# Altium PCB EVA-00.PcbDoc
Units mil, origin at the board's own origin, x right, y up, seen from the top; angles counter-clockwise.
Board outline 3000 x 2200 mil, 2 copper layers (Top Layer, Bottom Layer), stack 57.918 mil thick; 30 components, 25 nets, 139 pads, 31 vias.
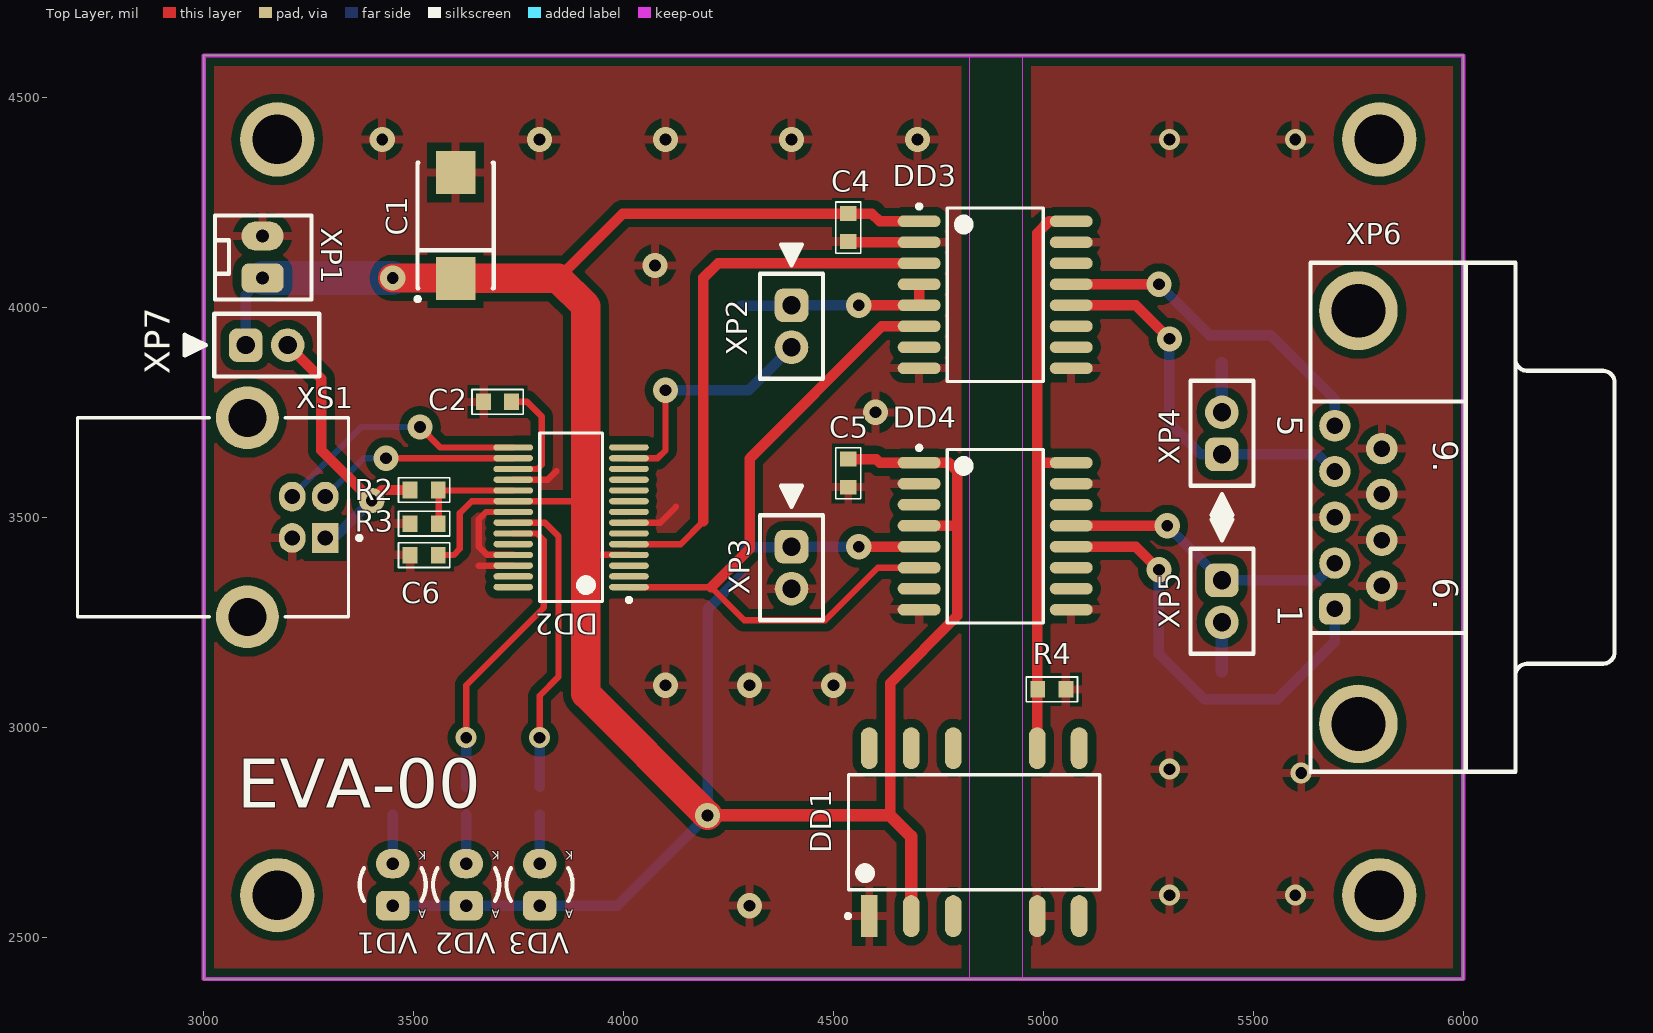
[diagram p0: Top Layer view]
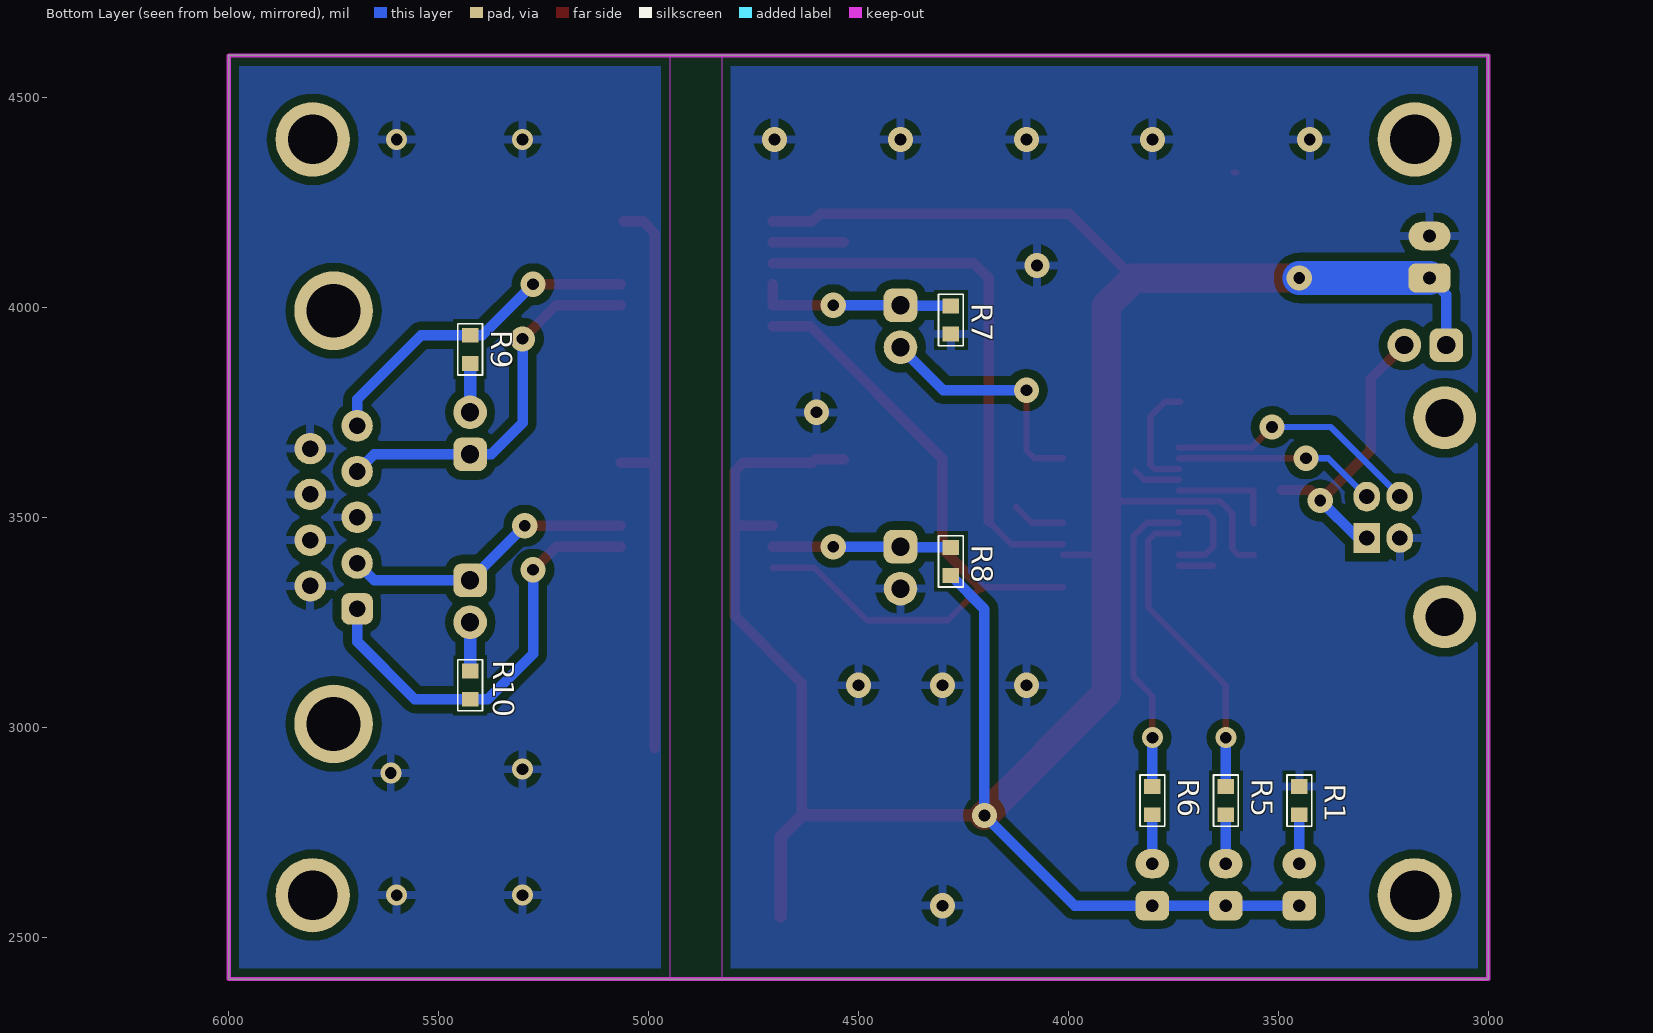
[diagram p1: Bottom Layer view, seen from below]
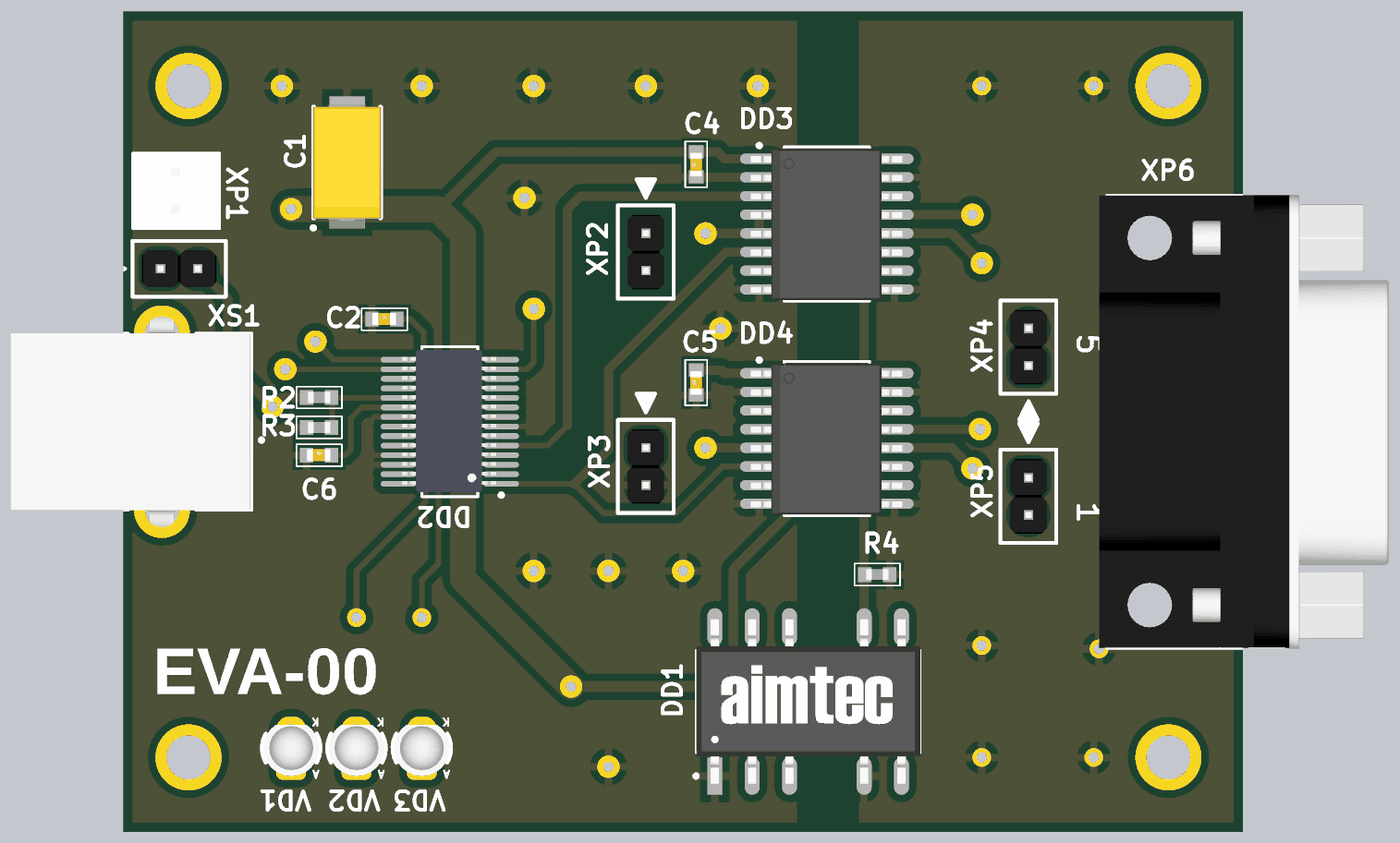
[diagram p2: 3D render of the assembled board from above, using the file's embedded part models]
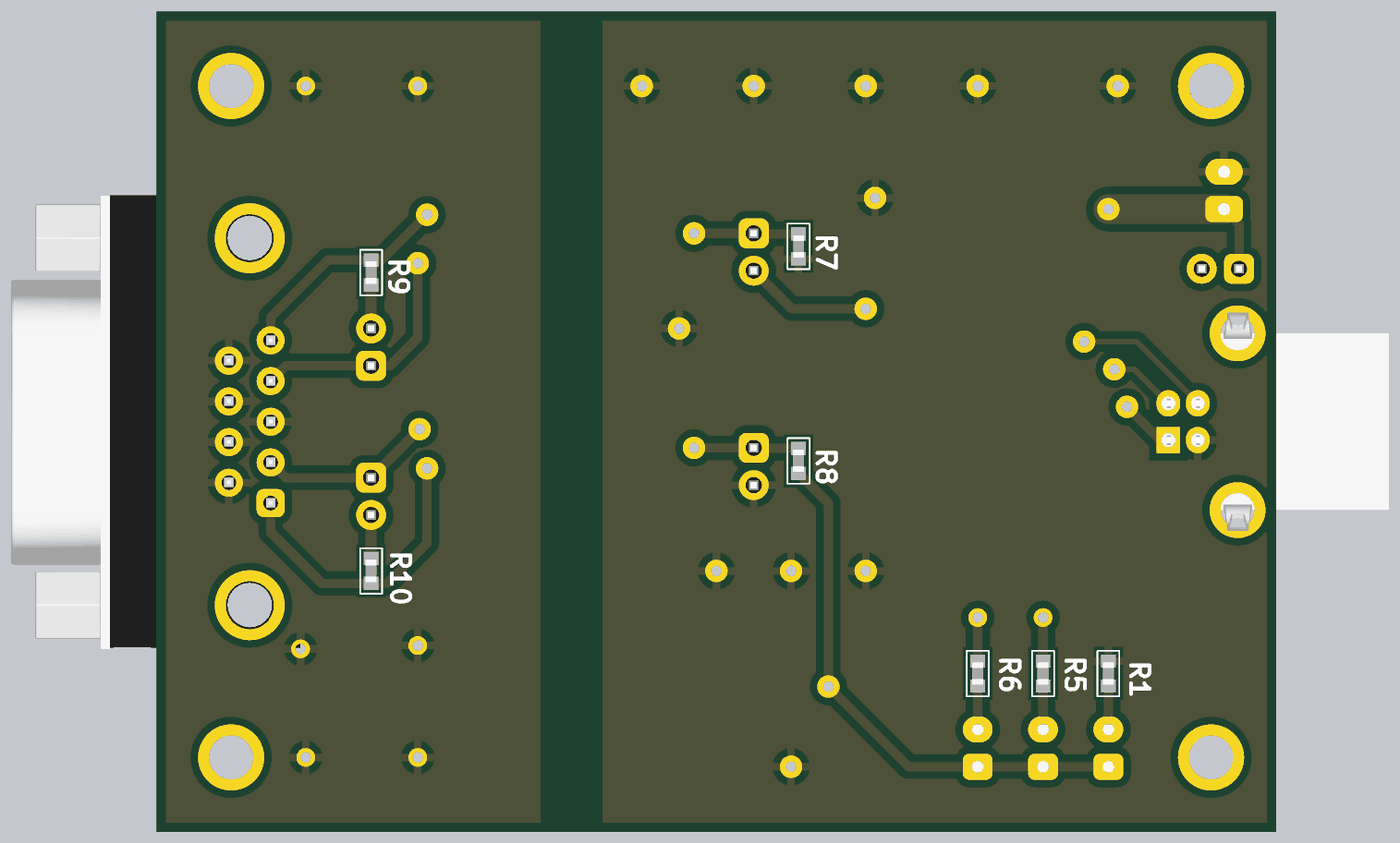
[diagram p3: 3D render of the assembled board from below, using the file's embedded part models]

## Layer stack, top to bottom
Top Layer: signal copper 1.4
Dielectric: core 55.1181, FR-4, Dk 4.8
Bottom Layer: signal copper 1.4

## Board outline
3000,2400 3000,4600 6000,4600 6000,2400

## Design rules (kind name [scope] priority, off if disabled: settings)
Clearance [All] p1: gap=10
DiffPairsRouting [All] p1: maxlimit=800 minlimit=10 mostfreqgap=25 maxuncoupledlength=500
PolygonConnect [All] p1: connectstyle=Relief reliefconductorwidth=20 reliefentries=4 polygonreliefangle="90 Angle"
RoutingVias [All] p1: holewidth=28 width=60 viastyle="Through Hole" minholewidth=28 minwidth=50 maxholewidth=28 maxwidth=60
SilkscreenOverComponentPads [All] p1: minsilkscreentomaskgap=10
SolderMaskExpansion [All] p1: expansion=0
Width [All] p1: maxlimit=80 minlimit=10 preferedwidth=15
26 further rules are at their usual default settings.

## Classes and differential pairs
differential pair D: +D_P -D_N
differential pair RS422: +RS422_P -RS422_N
differential pair RS485: +RS485_P -RS485_N

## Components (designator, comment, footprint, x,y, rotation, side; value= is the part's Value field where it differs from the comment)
C1 "Танталовый ЧИП конденсатор 220мкФ х 10В тип X" X-7343-43 3600,4195 r90 top
C2 "C <0603> 0,1 мкФ±20% 25В" 0603 3700,3775 r0 top
C4 "C <0603> 0,1 мкФ±20% 25В" 0603 4535,4190 r90 top
C5 "C <0603> 0,1 мкФ±20% 25В" 0603 4535,3605 r90 top
C6 "C <0603> 0,1 мкФ±20% 25В" 0603 3525,3410 r0 top
DD1 "AM1L-0505SH30-NZ" SMD12 4835,2750 r90 top
DD2 "FT232RL" "SSOP-28 (MO-150-AH)" 3875,3500 r180 top
DD3 "ADM2483BRWZ" "SOIC-16 (MS-013-AA)" 4885,4030 r0 top
DD4 "ADM2483BRWZ" "SOIC-16 (MS-013-AA)" 4885,3455 r0 top
R1 "R0603-470 Ом-5%" 0603 3450,2825 r270 bottom
R2 "R0603-4,7кОм-5%" 0603 3525,3565 r180 top
R3 "R0603-10кОм-5%" 0603 3525,3485 r0 top
R4 "R0603-240 Ом-5%" 0603 5020,3090 r180 top
R5 "R0603-470 Ом-5%" 0603 3625,2825 r270 bottom
R6 "R0603-470 Ом-5%" 0603 3800,2825 r270 bottom
R7 "R0603-10кОм-5%" 0603 4280,3970 r90 bottom
R8 "R0603-10кОм-5%" 0603 4280,3395 r270 bottom
R9 "R0603-120 Ом-5%" 0603 5425,3900 r90 bottom
R10 "R0603-120 Ом-5%" 0603 5425,3100 r270 bottom
VD1 "LED_d3mm" LED_d3mm 3450,2625 r180 top
VD2 "LED_d3mm" LED_d3mm 3625,2625 r180 top
VD3 "LED_d3mm" LED_d3mm 3800,2625 r180 top
XP1 "WF-2" WF-2 3140,4070 r90 top
XP2 "PLS-2" PLS-2 4400,3955 r0 top
XP3 "PLS-2" PLS-2 4400,3380 r0 top
XP4 "PLS-2" PLS-2 5425,3700 r180 top
XP5 "PLS-2" PLS-2 5425,3300 r0 top
XP6 "DB9M" DB9M 5750,3500 r90 top
XP7 "PLS-2" PLS-2 3150,3910 r90 top
XS1 "USBB-1J" USBB-1J 3250,3500 r180 top

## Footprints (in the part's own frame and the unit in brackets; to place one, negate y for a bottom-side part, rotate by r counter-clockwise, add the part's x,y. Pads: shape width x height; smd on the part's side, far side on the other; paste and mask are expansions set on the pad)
0603 [mm]
  rect 0.9x1 smd: 1(-0.85,0) 2(0.85,0)
  silkscreen extent -1.55,-0.75 1.55,0.75, body extent -0.83,-0.39 0.77,0.41, height 0.3
DB9M [mm] "Connector; D Subminiature; 9 Position; Right Angle; Pitch 1.385 mm"
  rrect50% 1.905x1.905 hole 1: 1(-5.54,1.42)
  round 1.905 hole 1: 2(-2.77,1.42) 3(0,1.42) 4(2.77,1.42) 5(5.54,1.42) 6(-4.155,-1.42) 7(-1.385,-1.42) 8(1.385,-1.42) 9(4.155,-1.42)
  round 4.76 hole 3.26: 10(12.495,0) 11(-12.495,0)
  silkscreen extent -15.4,-15.5 15.4,2.9, body extent -15.47,-16.23 15.42,3.45, height 12.57
LED_d3mm [mil] "Светодиод. Диаметр - 3мм."
  rrect50% 80x70 hole 30: 1(0,50)
  oval 80x70 hole 30: 2(0,-50)
  silkscreen extent -79,-39 79,39, body extent -75,-63 75,75, height 256
PLS-2 [mil] "PLS-2 вилка штыревая 2.54мм 1x2 прямая"
  rrect50% 80x80 hole 43.31: 1(0,50)
  round 80 hole 43.31: 2(0,-50)
  silkscreen extent -75,-125 75,195, body extent -49,-100 49,100, height 335
SMD12 [mil] "MD12, 12-Leads, Body 15,2x7,5mm (max), Pitch 2,54mm, IPC Medium Density"
  rect 100x40 smd: 1(-200,250)
  oval 100x40 smd: 2(-200,150) 3(-200,50) 5(-200,-150) 6(-200,-250) 7(200,-250) 8(200,-150) 10(200,50) 11(200,150) 12(200,250)
  silkscreen extent -205,-299 137,305, body extent -221,-300 221,300, height 256
"SOIC-16 (MS-013-AA)" [mm] "SOIC, 16-Leads, Body 10.3x7.5mm, Pitch 1.27mm, IPC Low Density"
  oval 2.6x0.7 smd: 1(-4.6,4.445) 2(-4.6,3.175) 3(-4.6,1.905) 4(-4.6,0.635) 5(-4.6,-0.635) 6(-4.6,-1.905) 7(-4.6,-3.175) 8(-4.6,-4.445) 9(4.6,-4.445) 10(4.6,-3.175) 11(4.6,-1.905) 12(4.6,-0.635) 13(4.6,0.635) 14(4.6,1.905) 15(4.6,3.175) 16(4.6,4.445)
  silkscreen extent -4.72,-5.25 2.9,5.47, body extent -5.18,-5.18 5.12,5.12, height 2.65
"SSOP-28 (MO-150-AH)" [mm] "SOP, 28-Leads, Body 10,2x5,3mm (max), Pitch 0,65mm, IPC Low Density"
  oval 2.4x0.38 smd: 1(-3.5,4.225) 2(-3.5,3.575) 3(-3.5,2.925) 4(-3.5,2.275) 5(-3.5,1.625) 6(-3.5,0.975) 7(-3.5,0.325) 8(-3.5,-0.325) 9(-3.5,-0.975) 10(-3.5,-1.625) 11(-3.5,-2.275) 12(-3.5,-2.925) 13(-3.5,-3.575) 14(-3.5,-4.225) 15(3.5,-4.225) 16(3.5,-3.575) 17(3.5,-2.925) 18(3.5,-2.275) 19(3.5,-1.625) 20(3.5,-0.975) 21(3.5,-0.325) 22(3.5,0.325) 23(3.5,0.975) 24(3.5,1.625) 25(3.5,2.275) 26(3.5,2.925) 27(3.5,3.575) 28(3.5,4.225)
  silkscreen extent -3.63,-5.1 1.9,5.12, body extent -3.15,-4.9 3.25,4.8, height 0.98
USBB-1J [mm] "Разъем USB (м) на плату, тип B"
  rect 1.6x1.8 hole 0.92: 1(-1,1.25)
  oval 1.6x1.8 hole 0.92: 2(-1,-1.25) 3(1,-1.25) 4(1,1.25)
  round 3.8 hole 2.3: 5(3.71,6.02) 6(3.71,-6.02)
  silkscreen extent -3.18,-6.02 13.99,6.02, body extent -2.29,-7.45 14.01,7.45, height 11.1
WF-2 [mil] "Разъем питания 2 конт.(п) шаг 2,54 на плату"
  rrect50% 70x100 hole 31.5: 1(0,0)
  oval 70x100 hole 31.5: 2(100,0)
  silkscreen extent -51,-117 149,113, body extent -51,-117 149,113, height 468
X-7343-43 [mm] "Capacitor, SM Tantalum; Body 7.3 x 4.3 mm (LxW typ)"
  rect 2.6x2.4 smd: 1(-3.2,0) 2(3.2,0)
  silkscreen extent -4.57,-2.3 3.8,2.42, body extent -4.5,-2.32 4.5,2.34, height 3.91

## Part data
C1: "Конденсатор танталовый, 220мкФ х 10В, тип корпуса D (7343-31)"
DD1: "Series AM1L-NZ 1 Watt"
DD2: "USB UART Asynchronous Serial Data Transfer Chip, SSOP-28, Pb-Free"
DD3 DD4: "Half-Duplex, iCoupler Isolated RS-485 Transceiver"
XP1: "Разъем питания 2 конт.(п) шаг 2,54 на плату"
XP2 XP3 XP4 XP5 XP7: "PLS-2 вилка штыревая 2.54мм 1x2 прямая"
XP6: "Name Type Description    D-SUB9 M Footprint Connector; D Subminiature; 9 Position; Right Angle; Pitch 1.385 mm"
XS1: "Разъем USB (м) на плату, тип B"

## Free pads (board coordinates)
  round 177.17 hole 118.11: 0(3175,4400) 1(5800,4400) 2(5800,2600) 3(3175,2600)

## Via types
v1: diameter 60, hole 28, Top Layer to Bottom Layer, 23 vias
v2: diameter 50, hole 28, Top Layer to Bottom Layer, 8 vias

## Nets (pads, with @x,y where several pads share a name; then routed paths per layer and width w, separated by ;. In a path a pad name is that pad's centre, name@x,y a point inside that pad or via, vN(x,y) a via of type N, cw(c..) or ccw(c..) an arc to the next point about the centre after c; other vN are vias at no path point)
D_N: DD2.16 XS1.2 | length 485.7
  Top Layer w15: v1(3434.25,3640.75) DD2.16
  Bottom Layer w15: XS1.2 3380.91,3640.75 v1(3434.25,3640.75)
D_P: DD2.15 XS1.3 | length 624.9
  Top Layer w15: XS1.3 XS1.3@3210.63,3557.84 ; v1(3515,3715) 3563.66,3666.34 DD2.15
  Bottom Layer w15: XS1.3 3210.63,3550.77 3374.86,3715 v1(3515,3715)
GND: C1.2 C2.1 C4.1 C5.1 C6.1 DD1.1 DD2.7 DD2.18 DD2.21 DD2.25 DD2.26 DD3.2 DD3.8 DD4.2 DD4.8 R1.1 R3.1 R7.1 XP1.2 XP3.2 XS1.4 | length 740.9
  Top Layer w15: C1.2 C1.2@3605.98,4320.98 ; 3655.16,3384.84 DD2.26 ; DD2.25 3674.57,3410.43 3655,3430 3655,3495 3672.8,3512.8 DD2.21 ; DD2.18 3819.57,3589.57 3840,3610 ; DD2.7 4087.2,3487.2 4125,3525
  Top Layer w25: C4.1@4535,4155 4615,4155 DD3.2
  other v1: 4300,2575 4100,3100 4300,3100 4500,3100 4600,3750 4075,4100 3425,4400 3800,4400 4100,4400 4400,4400 4700,4400
GND2: DD1.5 DD3.9 DD3.15 DD4.9 DD4.15 R4.1 XP6.3 XP6.6 XP6.7 XP6.8 XP6.9
  other v2: 5300,2600 5600,2600 5614.02,2891 5300,2900 5300,4400 5600,4400
NetC2_2: C2.2 DD2.17 | length 272.9
  Top Layer w15: C2.2 3770,3775 3805,3740 3805,3625 3795.16,3615.16 DD2.17
NetDD2_1: DD2.1 DD3.6 DD4.6 | length 1654
  Top Layer w15: DD2.1 4208.66,3333.66 4287.32,3255 4480,3255 4605,3380 DD4.6
  Top Layer w25: 4208.66,3333.66 4300,3425 4300,3640 4615,3955 DD3.6
NetDD2_5: DD2.5 DD3.3 | length 1308
  Top Layer w15: DD2.5 4136.02,3436.02 4190,3490
  Top Layer w25: 4190,3490 4190,4070 4225,4105 DD3.3
NetDD2_13: DD2.13 XP2.2 | length 580.3
  Top Layer w15: DD2.13 4080.75,3640.75 4100,3660 v1(4100,3802.8)
  Bottom Layer w25: v1(4100,3802.8) 4297.8,3802.8 XP2.2
NetDD2_19: DD2.19 R2.1 R3.2 | length 257.1
  Top Layer w15: R3.2 3559.49,3486.02 3559.49,3563.98 DD2.19
NetDD2_22: DD2.22 R6.1 | length 736.3
  Top Layer w15: DD2.22 3812.8,3487.2 3845,3455 3845,3209.34 3845,3120 3800,3075 v2(3800,2975)
  Bottom Layer w25: R6.1 v2(3800,2975)
NetDD2_23: DD2.23 R5.1 | length 742.8
  Top Layer w15: v2(3625,2975) 3625,3100 3810,3285 3810,3445 3793.39,3461.61 DD2.23
  Bottom Layer w25: R5.1 v2(3625,2975)
NetDD3_4: DD3.4 DD3.5 R7.2 XP2.1 | length 474.5
  Top Layer w25: v1(4560,4005) DD3.5 DD3.4
  Bottom Layer w25: R7.2 4398.46,4003.46 XP2.1 v1(4560,4005)
NetDD4_5: DD4.5 R8.1 XP3.1 | length 424.5
  Top Layer w25: v1(4560,3430) DD4.5
  Bottom Layer w25: R8.1 4398.46,3428.46 XP3.1 v1(4560,3430)
NetR1_2: R1.2 VD1.2 | length 116.5
  Bottom Layer w25: VD1.2 R1.2
NetR5_2: R5.2 VD2.2 | length 116.5
  Bottom Layer w25: VD2.2 R5.2
NetR6_2: R6.2 VD3.2 | length 116.5
  Bottom Layer w25: VD3.2 R6.2
NetR9_1: R9.1 XP4.2 | length 116.5
  Bottom Layer w30: XP4.2 R9.1
NetR10_1: R10.1 XP5.2 | length 116.5
  Bottom Layer w30: R10.1 XP5.2
RS422_N: DD4.13 XP5.1 XP6.2 | length 698.8
  Top Layer w25: DD4.13 v1(5295,3480)
  Bottom Layer w25: v1(5295,3480) XP5.1 5653.15,3350 XP6.2
RS422_P: DD4.12 R10.2 XP6.1 | length 1030.5
  Top Layer w25: DD4.12 5220,3430 v1(5275,3375)
  Bottom Layer w25: v1(5275,3375) 5275,3175 5383.46,3066.54 R10.2 5556.54,3066.54 5694.09,3204.09 XP6.1
RS485_N: DD3.13 R9.2 XP6.5 | length 804.3
  Top Layer w25: DD3.13 v1(5275,4055)
  Bottom Layer w25: v1(5275,4055) 5396.54,3933.46 R9.2 5541.54,3933.46 5694.09,3780.91 XP6.5
RS485_P: DD3.12 XP4.1 XP6.4 | length 909.2
  Top Layer w25: DD3.12 5220,4005 v1(5300,3925)
  Bottom Layer w25: v1(5300,3925) 5300,3725 5375,3650 XP4.1 5653.15,3650 XP6.4
USB_VCC: R2.2 XP7.2 XS1.1 | length 702.3
  Top Layer w25: XP7.2 3280,3830 3280,3660 v1(3400,3540) 3425,3565 R2.2
  Bottom Layer w25: XS1.1 3310.79,3450.79 v1(3400,3540)
VCC: C1.1 C4.2 C5.2 C6.2 DD1.2 DD2.4 DD2.20 DD3.1 DD4.1 DD4.4 R8.2 VD1.1 VD2.1 VD3.1 XP1.1 XP7.1 | length 7185.7
  Top Layer w15: C6.2 3595,3410 3610,3425 3610,3510 3638.39,3538.39 DD2.20 3908.39,3538.39 3910,3540 ; 3910,3410 3910.43,3410.43 DD2.4
  Top Layer w25: C1.1@3599.02,4070 C1.1 ; 3844.02,4069.02 3998.46,4223.46 C4.2 4591.54,4223.46 4610,4205 DD3.1 ; C5.2 4601.54,3638.46 4610,3630 DD4.1 4775,3630 4795,3610 4795,3480 ; 4635,2790 4635,3105 4795,3265 4795,3480 ; DD4.4 4795,3480
  Top Layer w30: v1(4200,2790) 4635,2790 4685,2740 DD1.2
  Top Layer w70: v1(3450,4070) C1.1@3599.02,4070 ; C1.1 3844.02,4069.02 3910,4003.03 3910,3540 3910,3410 3910,3080 v1(4200,2790)
  Bottom Layer w25: XP7.1 3100,4030 XP1.1 ; VD1.1 VD2.1 VD3.1 3985,2575 v1(4200,2790) 4200,3281.54 R8.2
  Bottom Layer w80: XP1.1 v1(3450,4070)
VCC1: DD1.8 DD3.16 DD4.16 R4.2 | length 1393.2
  Top Layer w25: DD1.8 4985,3230 4985,3630 ; DD3.16@5058.66,4205 5013.25,4205 4985,4176.75 4985,3630 ; DD4.16 4985,3630
pads on no net: DD1.3 DD1.6 DD1.7 DD1.10 DD1.11 DD1.12 DD2.2 DD2.3 DD2.6 DD2.8 DD2.9 DD2.10 DD2.11 DD2.12 DD2.14 DD2.24 DD2.27 DD2.28 DD3.7 DD3.10 DD3.11 DD3.14 DD4.3 DD4.7 DD4.10 DD4.11 DD4.14 XP6.10 XP6.11 XS1.5 XS1.6

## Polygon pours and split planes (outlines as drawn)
GND2 on Top Layer "Bottom Layer-No Net" (solid, remove dead copper, pour order 1001): 4950,4600 6000,4600 6000,2400 4950,2400
GND on Top Layer "Bottom Layer-No Net" (solid, remove dead copper, pour order 6): 3000,4600 4825,4600 4825,2400 3000,2400
GND2 on Bottom Layer "Bottom Layer-No Net" (solid, pour order 1003): 4950,4600 6000,4600 6000,2400 4950,2400
GND on Bottom Layer "Bottom Layer-No Net" (solid, remove dead copper, pour order 8): 3000,2400 4825,2400 4825,4600 3000,4600

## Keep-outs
Keep-Out Layer:
  the board outline again, w10
Multi-Layer:
  region: 4825,4600 4950,4600 4950,2400 4825,2400

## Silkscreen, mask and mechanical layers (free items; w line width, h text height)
Top Overlay:
  text "EVA-00" at 3080,2770 h200

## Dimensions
3000,4600 to 3000,2400 on Mechanical 15
3000,4600 to 6000,4600 on Mechanical 15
